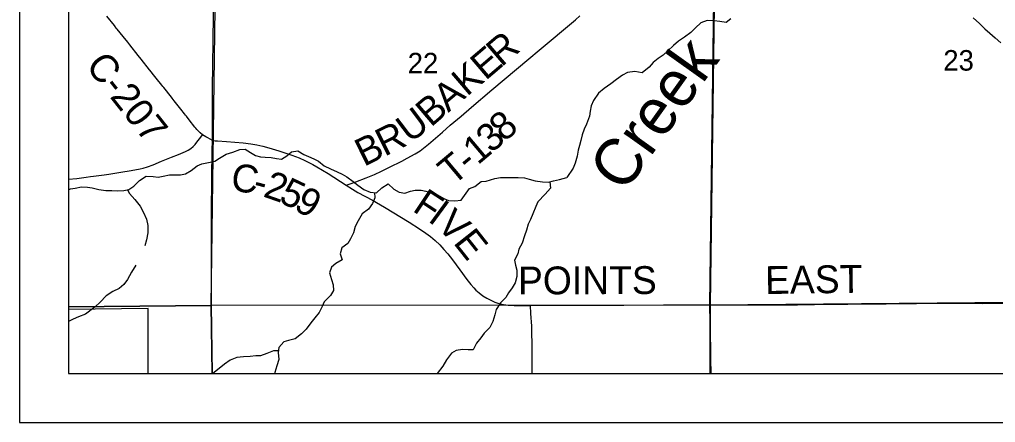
# Model space of a CAD drawing. Extents: x 0 to 34, y 0 to 22.
# Drawn here: x 2 to 3.99, y 14 to 14.823 of the extents above; entities that cross this region are included whole.
import ezdxf

# ---------------------------------------------------------------- set-up
doc = ezdxf.new("R2010")
doc.units = 0
for name, color, linetype in [('Default', 7, 'Continuous'), ('GM_X_County_Road', 7, 'Continuous'), ('GM_X_County_Road_Text', 7, 'Continuous'), ('GM_X_Minor_River', 7, 'Continuous'), ('GM_X_Minor_River_Text', 7, 'Continuous'), ('GM_X_Section', 7, 'Continuous'), ('GM_X_Section_Text', 7, 'Continuous'), ('GM_X_State_Route', 7, 'Continuous'), ('GM_X_Township_Road', 7, 'Continuous'), ('GM_X_Township_Road_Text', 7, 'Continuous'), ('SH_Cut_Line', 7, 'Continuous'), ('SH_Data', 7, 'Continuous')]:
    doc.layers.add(name, color=color, linetype=linetype)

msp = doc.modelspace()

# ---------------------------------------------------------------- linework, layer by layer
at = {"layer": 'Default'}
for points in [[(2.1, 18.2607), (2.1, 14.1), (3.4093, 14.1), (3.4089, 14.1297), (3.4088, 14.1527), (3.4084, 14.1769), (3.4082, 14.204), (3.4076, 14.2404), (3.4184, 15.0709)], [(3.4184, 15.0709), (3.4076, 14.2404), (3.4082, 14.204), (3.4084, 14.1769), (3.4088, 14.1527), (3.4089, 14.1297), (3.4093, 14.1), (7.4893, 14.1)]]:
    msp.add_lwpolyline(points, dxfattribs=at)
for points in [[(2.1, 15.2441), (2.1, 14.2363), (2.3909, 14.2388), (2.4044, 15.2506)], [(3.4083, 14.1), (4.4126, 14.1), (4.4107, 14.2482), (3.4079, 14.2395)], [(2.1, 14.2363), (2.1, 14.1), (2.3926, 14.1), (2.3909, 14.2388)], [(2.1, 14.2306), (2.1, 14.1), (2.2624, 14.1), (2.2624, 14.2327)], [(2.3926, 14.1), (3.4083, 14.1), (3.4079, 14.2395), (2.3909, 14.2388)]]:
    msp.add_lwpolyline(points, close=True, dxfattribs=at)
at = {"layer": 'GM_X_County_Road'}
for points in [[(2.3734, 14.5871), (2.368, 14.5913), (2.3636, 14.5959), (2.3614, 14.5981), (2.3593, 14.6005), (2.3573, 14.6029), (2.3458, 14.6176), (2.3402, 14.625), (2.3383, 14.6275), (2.3364, 14.6299), (2.3288, 14.6397), (2.3154, 14.6568), (2.3134, 14.6592), (2.3115, 14.6617), (2.3096, 14.6641), (2.294, 14.6835), (2.2921, 14.6859), (2.2902, 14.6884), (2.2786, 14.703), (2.2708, 14.7127), (2.2689, 14.7151), (2.265, 14.72), (2.2477, 14.7419), (2.2419, 14.7492), (2.2246, 14.7711), (2.2207, 14.776), (2.211, 14.7881), (2.1993, 14.8027), (2.1974, 14.8051), (2.1935, 14.81), (2.1781, 14.8294)], [(2.1, 14.4965), (2.1172, 14.4982), (2.1357, 14.5006), (2.1446, 14.5019), (2.1509, 14.5028), (2.1726, 14.5058), (2.1819, 14.5071), (2.2064, 14.5111), (2.2278, 14.5143), (2.246, 14.5177), (2.252, 14.5191), (2.2608, 14.5219), (2.2724, 14.5261), (2.2897, 14.5333), (2.3098, 14.5415), (2.3242, 14.5473), (2.3385, 14.5534), (2.344, 14.5561), (2.3492, 14.5593), (2.3539, 14.5631), (2.3582, 14.5674), (2.3639, 14.5747), (2.3677, 14.5797), (2.3734, 14.5871)], [(2.3932, 14.5756), (2.384, 14.5807), (2.3796, 14.5832), (2.3734, 14.5871)], [(2.3932, 14.5756), (2.3986, 14.575), (2.4034, 14.5748), (2.422, 14.5734), (2.4561, 14.5705), (2.4716, 14.5687), (2.4839, 14.5666), (2.4961, 14.564), (2.5081, 14.5608), (2.5289, 14.5544), (2.5555, 14.5454), (2.5701, 14.5399), (2.5818, 14.5347), (2.5984, 14.5267), (2.6064, 14.5221), (2.6293, 14.5081), (2.6663, 14.4841)], [(2.6663, 14.4841), (2.6789, 14.476), (2.6895, 14.4697), (2.7196, 14.4535), (2.7439, 14.4395), (2.7944, 14.4089), (2.8154, 14.3955), (2.8283, 14.3867), (2.8383, 14.3793), (2.8478, 14.3712), (2.8568, 14.3625), (2.8653, 14.3534), (2.8735, 14.344), (2.8831, 14.3318), (2.8978, 14.3117), (2.9123, 14.2915), (2.92, 14.2818), (2.926, 14.2748), (2.9303, 14.2704), (2.9373, 14.2643), (2.9448, 14.2588), (2.9526, 14.2539), (2.9608, 14.2495), (2.9692, 14.2459), (2.9751, 14.2438), (2.981, 14.242), (2.987, 14.2408), (2.9961, 14.2397), (3.0085, 14.2391), (3.0334, 14.2391), (3.0419, 14.2391)], [(3.0419, 14.2391), (3.1265, 14.2395), (3.1701, 14.2396), (3.2322, 14.2396), (3.3131, 14.2399), (3.3846, 14.2398), (3.4078, 14.2398)], [(3.4078, 14.2398), (3.4343, 14.2398), (3.5586, 14.24), (3.5865, 14.2403), (3.6207, 14.2409), (3.6891, 14.2412), (3.7668, 14.2425), (3.829, 14.2428), (3.9005, 14.2433), (3.9626, 14.243), (4.0403, 14.2435), (4.1211, 14.2448), (4.1646, 14.2453), (4.2019, 14.2459), (4.2206, 14.2457), (4.2305, 14.2456)]]:
    msp.add_lwpolyline(points, dxfattribs=at)
at = {"layer": 'GM_X_Minor_River'}
for points in [[(3.9444, 14.8259), (3.9573, 14.8141), (3.9686, 14.8035), (3.9785, 14.7948), (3.9891, 14.7853), (4.0008, 14.7747)], [(3.4501, 14.8239), (3.4406, 14.8167), (3.4277, 14.8182), (3.4167, 14.8201), (3.4019, 14.8205), (3.389, 14.8159), (3.378, 14.8057), (3.3689, 14.7958), (3.356, 14.7867), (3.3435, 14.778), (3.3333, 14.7697), (3.3219, 14.7583), (3.3124, 14.7496), (3.3022, 14.7427), (3.2923, 14.7348), (3.2836, 14.7253), (3.2696, 14.7139), (3.2544, 14.7162), (3.2396, 14.7146), (3.2298, 14.7086), (3.2173, 14.7002), (3.2059, 14.6915), (3.1922, 14.682), (3.1805, 14.6725), (3.1702, 14.6574), (3.1657, 14.646), (3.1634, 14.6354), (3.1619, 14.6251), (3.1562, 14.6088), (3.1512, 14.5986), (3.1474, 14.5872), (3.1444, 14.5754), (3.1421, 14.5652), (3.1391, 14.5557), (3.1368, 14.5439), (3.133, 14.5295), (3.1288, 14.5193), (3.1159, 14.4999)], [(2.1, 14.4748), (2.1042, 14.4766), (2.1137, 14.4785), (2.1266, 14.4808), (2.1383, 14.4804), (2.1482, 14.4789), (2.1615, 14.4755), (2.1763, 14.4736), (2.1885, 14.4736), (2.1995, 14.4729), (2.2128, 14.4733), (2.2226, 14.4752), (2.2329, 14.482), (2.2443, 14.4942), (2.2579, 14.5029), (2.2727, 14.5022), (2.283, 14.5006), (2.2928, 14.5029), (2.3058, 14.5056), (2.3187, 14.5056), (2.3285, 14.5056), (2.3384, 14.5075), (2.3502, 14.514), (2.3623, 14.5238), (2.3718, 14.528), (2.3851, 14.5307), (2.398, 14.5334), (2.4079, 14.5394), (2.4212, 14.5478), (2.4348, 14.5516), (2.4489, 14.5569), (2.4599, 14.5577), (2.4713, 14.5509), (2.4815, 14.5448), (2.4914, 14.5421), (2.5009, 14.5418), (2.5134, 14.541), (2.524, 14.5387), (2.5339, 14.5376), (2.5449, 14.5444), (2.5544, 14.5524), (2.5673, 14.5547), (2.5795, 14.5471), (2.589, 14.5429), (2.6004, 14.538), (2.6098, 14.5335), (2.6212, 14.524), (2.6342, 14.5179)], [(2.6342, 14.5179), (2.6478, 14.5118), (2.6577, 14.5069), (2.6676, 14.5016), (2.6801, 14.4917), (2.6896, 14.4841), (2.7021, 14.4754), (2.715, 14.4704), (2.7279, 14.4689), (2.7386, 14.4788), (2.7519, 14.4872), (2.7633, 14.4765), (2.7739, 14.4701), (2.7857, 14.4682), (2.797, 14.472), (2.8069, 14.4739), (2.8187, 14.4739), (2.8282, 14.472), (2.8426, 14.4682), (2.8521, 14.4644), (2.8654, 14.4572), (2.8749, 14.4534), (2.8878, 14.4523), (2.9003, 14.4538), (2.9109, 14.4682), (2.9174, 14.4777), (2.9284, 14.4819), (2.9413, 14.4922), (2.9512, 14.4926), (2.969, 14.4983), (2.9808, 14.5002), (2.9907, 14.4998), (3.0024, 14.4998), (3.0165, 14.4998), (3.0294, 14.4991), (3.0389, 14.4968), (3.0514, 14.4934), (3.0666, 14.4915), (3.0784, 14.4904), (3.0886, 14.4934), (3.1008, 14.4957), (3.1159, 14.4999)], [(3.081, 14.4911), (3.0829, 14.4782), (3.0715, 14.466), (3.0567, 14.4501), (3.0529, 14.4406), (3.0469, 14.4261), (3.0419, 14.414), (3.0374, 14.4045), (3.0336, 14.3927), (3.0298, 14.3813), (3.0249, 14.3657), (3.0181, 14.3536), (3.0158, 14.3441), (3.0093, 14.3315), (3.0116, 14.3213), (3.0139, 14.3106), (3.0143, 14.2981), (3.0109, 14.2848), (3.0048, 14.2749), (2.9972, 14.2647), (2.9919, 14.2552), (2.9809, 14.2442), (2.9718, 14.2309), (2.9691, 14.2198), (2.965, 14.2062), (2.9593, 14.194), (2.9471, 14.1826), (2.9407, 14.1727), (2.9316, 14.1617), (2.9251, 14.1484), (2.9149, 14.148), (2.9035, 14.1491), (2.8906, 14.1472), (2.8811, 14.1412), (2.8709, 14.1282), (2.8633, 14.1149), (2.8518, 14.1)], [(2.2199, 14.4746), (2.2241, 14.4676), (2.2348, 14.455), (2.2458, 14.4414), (2.253, 14.4288), (2.2587, 14.4152), (2.2614, 14.4019), (2.2618, 14.3874), (2.2591, 14.3726), (2.2553, 14.3608)], [(2.7241, 14.4694), (2.7242, 14.4587), (2.72, 14.4473), (2.7113, 14.4351), (2.6984, 14.426), (2.6908, 14.4119), (2.6847, 14.4002), (2.6809, 14.3872), (2.6752, 14.3751), (2.6691, 14.3656), (2.657, 14.3565), (2.654, 14.3439), (2.6582, 14.3318), (2.6452, 14.3242), (2.6358, 14.3169), (2.6323, 14.3055), (2.6358, 14.2919), (2.6396, 14.2812), (2.64, 14.2691), (2.6343, 14.2592), (2.6214, 14.2463), (2.6168, 14.2364), (2.6111, 14.2242), (2.6024, 14.2136), (2.5937, 14.2033), (2.5846, 14.1904), (2.5751, 14.1809), (2.5622, 14.171), (2.5485, 14.1676), (2.539, 14.1649), (2.5288, 14.1528), (2.5273, 14.1425), (2.5288, 14.1285), (2.5246, 14.1159), (2.5204, 14.1019), (2.5204, 14.1)], [(2.2375, 14.3213), (2.2284, 14.3069), (2.2201, 14.2921), (2.2128, 14.2818), (2.2034, 14.2738), (2.1901, 14.2674), (2.1764, 14.2582), (2.1643, 14.2453), (2.154, 14.2358), (2.1343, 14.2214), (2.1206, 14.2157), (2.1096, 14.2107), (2.1, 14.2062)], [(2.5278, 14.1462), (2.5178, 14.1463), (2.5041, 14.1406), (2.4916, 14.1357), (2.4821, 14.1357), (2.4703, 14.1345), (2.457, 14.1338), (2.443, 14.1326), (2.4297, 14.1269), (2.4179, 14.1189), (2.4039, 14.1075), (2.3942, 14.1)]]:
    msp.add_lwpolyline(points, dxfattribs=at)
at = {"layer": 'GM_X_Section'}
for points in [[(3.4219, 15.2567), (3.4079, 14.2395), (2.3909, 14.2388), (2.4044, 15.2506)], [(4.4235, 15.2608), (4.4107, 14.2482), (3.4079, 14.2395), (3.4219, 15.2567)]]:
    msp.add_lwpolyline(points, close=True, dxfattribs=at)
at = {"layer": 'GM_X_State_Route'}
for points in [[(2.3932, 14.5756), (2.3938, 14.5861), (2.3937, 14.6481), (2.3938, 14.6916), (2.3943, 14.7196), (2.3951, 14.7881), (2.3964, 14.8563), (2.3989, 14.9744), (2.4025, 15.1546), (2.4041, 15.2602), (2.4048, 15.341), (2.4051, 15.4125), (2.4055, 15.6176), (2.4052, 15.6612), (2.4053, 15.7233), (2.4056, 15.7606), (2.4055, 15.8197), (2.4057, 15.8713), (2.4056, 15.9067), (2.4056, 15.9968), (2.4055, 16.0932)], [(2.3929, 14.1), (2.3928, 14.1075), (2.392, 14.1883), (2.3915, 14.2442), (2.3914, 14.2731), (2.3915, 14.3158), (2.3914, 14.4275), (2.392, 14.4993), (2.3928, 14.5548), (2.3932, 14.5756)]]:
    msp.add_lwpolyline(points, dxfattribs=at)
at = {"layer": 'GM_X_Township_Road'}
for points in [[(2.6663, 14.4841), (2.6741, 14.4871), (2.6859, 14.4915), (2.7069, 14.4993), (2.7241, 14.5062), (2.7382, 14.5127), (2.7547, 14.5213), (2.7798, 14.5336), (2.7907, 14.5395), (2.8068, 14.5482), (2.8167, 14.5544), (2.8342, 14.5684), (2.8482, 14.5801), (2.8624, 14.5923), (2.8783, 14.6068), (2.8928, 14.6188), (2.9006, 14.6251), (2.9215, 14.6438), (2.9633, 14.6793), (3.0383, 14.742), (3.0596, 14.7599), (3.1335, 14.8217), (3.1428, 14.8299)], [(3.0456, 14.1), (3.0456, 14.106), (3.0452, 14.1422), (3.045, 14.1636), (3.0449, 14.1793), (3.0443, 14.1966), (3.0429, 14.2224), (3.0419, 14.2391)], [(3.409, 14.1421), (3.409, 14.1521), (3.4086, 14.1763), (3.4084, 14.2035), (3.4078, 14.2398)], [(3.4095, 14.1), (3.4091, 14.1291), (3.409, 14.1421)]]:
    msp.add_lwpolyline(points, dxfattribs=at)
at = {"layer": 'SH_Cut_Line'}
msp.add_lwpolyline([(2.1, 20.9), (2.1, 14.1), (7.4893, 14.1)], dxfattribs=at)
at = {"layer": 'SH_Data'}
for p, q in [((2, 21), (2, 14)), ((2.1, 20.9), (2.1, 14.1)), ((2.1, 14.1), (8.9, 14.1)), ((2.1, 14.1), (2.1, 14.1)), ((2, 14), (9, 14))]:
    msp.add_line(p, q, dxfattribs=at)

# ---------------------------------------------------------------- texts
at = {"layer": 'GM_X_County_Road_Text'}
for s, height, rotation, p in [('C-207', 0.05682, 308.2791, (2.1332, 14.7277)), ('C', 0.0568, 351.4007, (2.4288, 14.4741)), ('2', 0.0568, 340.678, (2.4948, 14.4618)), ('-', 0.0568, 345.2235, (2.4734, 14.4674)), ('5', 0.0568, 334.7011, (2.5264, 14.4509)), ('9', 0.0568, 329.0693, (2.5567, 14.4366)), ('F', 0.0568, 326.4971, (2.7993, 14.4328)), ('I', 0.0568, 323.7718, (2.8307, 14.412)), ('V', 0.0568, 316.6797, (2.8481, 14.3994)), ('E', 0.0568, 308.3881, (2.883, 14.3667)), ('POINTS', 0.05682, 0.1956, (3.0165, 14.2613)), ('EAST', 0.05682, 0.8173, (3.5205, 14.2621))]:
    msp.add_text(s, height=height, rotation=rotation, dxfattribs=at).set_placement(p)
at = {"layer": 'GM_X_Minor_River_Text'}
msp.add_text('Creek', height=0.09473, rotation=54.4656, dxfattribs=at).set_placement((3.2327, 14.4659))
at = {"layer": 'GM_X_Section_Text'}
for s, p in [('22', (2.7915, 14.7126)), ('23', (3.8836, 14.7182))]:
    msp.add_text(s, height=0.04186, rotation=0, dxfattribs=at).set_placement(p)
at = {"layer": 'GM_X_Township_Road_Text'}
for s, rotation, p in [('R', 40.5193, (2.9825, 14.7243)), ('E', 40.4805, (2.9502, 14.6967)), ('K', 40.4721, (2.9121, 14.6642)), ('A', 40.4749, (2.8741, 14.6317)), ('B', 40.5412, (2.8387, 14.6014)), ('U', 36.9167, (2.7956, 14.5689)), ('8', 40.7864, (2.9883, 14.5712)), ('R', 26.4974, (2.7443, 14.5422)), ('3', 41.6497, (2.9623, 14.5481)), ('B', 26.3556, (2.7023, 14.5214)), ('1', 40.1905, (2.9344, 14.5244)), ('T', 39.957, (2.8837, 14.482)), ('-', 40.0101, (2.9164, 14.5093))]:
    msp.add_text(s, height=0.0568, rotation=rotation, dxfattribs=at).set_placement(p)

doc.saveas('drawing.dxf')
